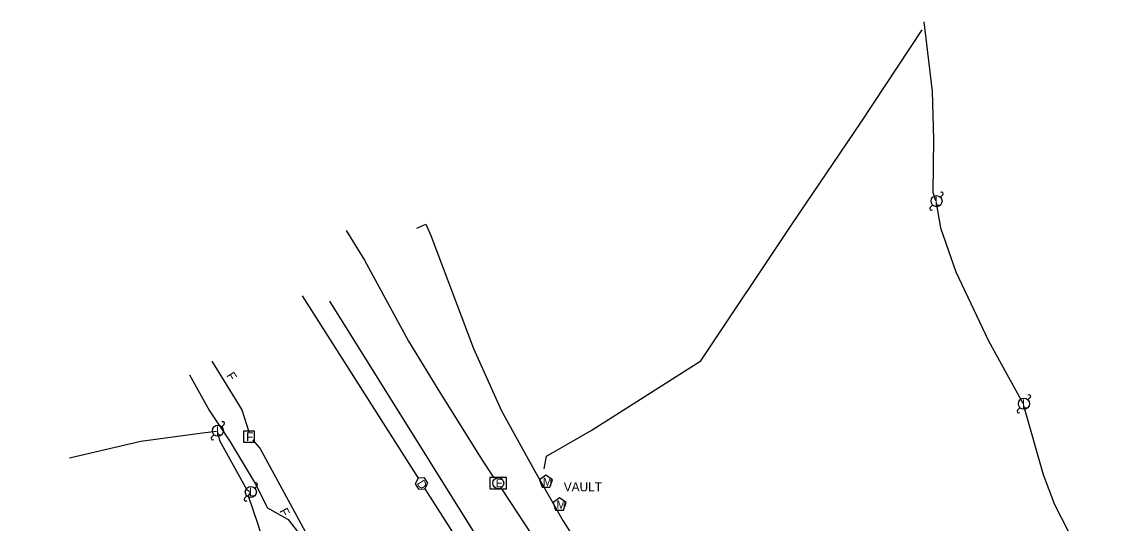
# Model space of a CAD drawing. Extents: x 1741604 to 1825760, y 1164229 to 1194908.
# Drawn here: x 1788051.3 to 1788542.1, y 1183770.9 to 1183996.9 of the extents above; entities that cross this region are included whole.
import ezdxf

# ---------------------------------------------------------------- set-up
doc = ezdxf.new("R2010")
doc.units = 0
for name, color, linetype in [('RD_EX_SU_Elec', 7, 'Continuous'), ('RD_EX_SU_Gas', 7, 'Continuous'), ('RD_EX_SU_H2O', 7, 'Continuous'), ('RD_EX_SU_Pole', 7, 'Continuous'), ('RD_EX_SU_Telecom', 7, 'Continuous'), ('RD_EX_SU_TX_H2O', 7, 'Continuous'), ('RD_EX_SU_TX_Telecom', 7, 'Continuous')]:
    doc.layers.add(name, color=color, linetype=linetype)

# ---------------------------------------------------------------- blocks, each defined once
blk = doc.blocks.new('SUE_WM')
at = {"layer": 'RD_EX_SU_H2O'}
blk.add_lwpolyline([(0, 3.05), (-2.9, 0.94), (-1.79, -2.47), (1.79, -2.47), (2.9, 0.94)], close=True, dxfattribs=at)
blk.add_text('M', height=3.75, dxfattribs=at).set_placement((-1.43, -1.88))

msp = doc.modelspace()

# ---------------------------------------------------------------- linework, layer by layer
at = {"layer": 'RD_EX_SU_Elec'}
for points in [[(1788458.01, 1183996.92), (1788461.77, 1183965.48), (1788462.39, 1183943.97), (1788462.12, 1183920.08), (1788463.28, 1183916.42)], [(1788463.63, 1183915.38), (1788465.57, 1183904.08), (1788472.46, 1183884.24), (1788487.22, 1183853.04), (1788502.67, 1183825.07)], [(1788197.52, 1183902.86), (1788205.84, 1183889.48), (1788225.65, 1183852.96), (1788238.84, 1183831.27), (1788258.92, 1183799.26), (1788263.83, 1183791.85)], [(1788502.94, 1183824.03), (1788511.78, 1183792.86), (1788517.03, 1183779.34), (1788540.86, 1183732.77), (1788542.1, 1183732.22)], [(1788072.85, 1183800.43), (1788105.03, 1183807.94), (1788132.72, 1183811.6), (1788139.05, 1183812.35)], [(1788139.59, 1183811.98), (1788140.51, 1183808.16), (1788147.36, 1183795.66), (1788152.83, 1183785.9), (1788154.16, 1183785.23)], [(1788154.27, 1183784.6), (1788153.45, 1183783.2), (1788157.66, 1183770.44), (1788163.13, 1183753.07), (1788169.12, 1183740.27)], [(1788267.93, 1183785.96), (1788281.5, 1183765.34), (1788301.05, 1183738.22), (1788315.42, 1183716.09), (1788322.04, 1183702.13), (1788344.59, 1183668.1), (1788364.36, 1183642.25), (1788376.14, 1183629.81), (1788408.98, 1183603.56), (1788419.49, 1183593.98), (1788443.59, 1183579.95), (1788457.69, 1183566.89)]]:
    msp.add_lwpolyline(points, dxfattribs=at)
msp.add_lwpolyline([(1788269.86, 1183791.45), (1788262.42, 1183791.45), (1788262.42, 1183786.45), (1788269.86, 1183786.45)], close=True, dxfattribs=at)
msp.add_circle((1788266.14, 1183788.95), 2.47, dxfattribs=at)
at = {"layer": 'RD_EX_SU_Gas'}
for p, q in [((1788177.66, 1183873.42), (1788229.98, 1183791.25)), ((1788233.08, 1183786.38), (1788290.45, 1183696.27))]:
    msp.add_line(p, q, dxfattribs=at)
msp.add_lwpolyline([(1788233.08, 1183786.38), (1788234.41, 1183788.94), (1788232.86, 1183791.38), (1788229.98, 1183791.25), (1788228.65, 1183788.69), (1788230.2, 1183786.25)], close=True, dxfattribs=at)
at = {"layer": 'RD_EX_SU_H2O'}
for points in [[(1788286.9, 1183795.45), (1788287.86, 1183801.08), (1788307.97, 1183812.62), (1788357.48, 1183844.1), (1788398.56, 1183905.52), (1788429.79, 1183951.73), (1788457.27, 1183993.28)], [(1788229.41, 1183903.94), (1788233.43, 1183905.72), (1788235.73, 1183900.64), (1788255.02, 1183849.63), (1788267.63, 1183821.5), (1788282.62, 1183794.43), (1788295.32, 1183772.14)], [(1788190.07, 1183871.02), (1788257.58, 1183762.93), (1788303.91, 1183698.73)], [(1788295.32, 1183772.14), (1788303.92, 1183758.42), (1788316.07, 1183737.45), (1788330.52, 1183715.26), (1788335.33, 1183706.88)]]:
    msp.add_lwpolyline(points, dxfattribs=at)
at = {"layer": 'RD_EX_SU_Pole'}
for p, q in [((1788465.55, 1183917.84), (1788466.61, 1183918.9)), ((1788460.96, 1183913.25), (1788462.02, 1183914.31)), ((1788504.94, 1183826.5), (1788506, 1183827.56)), ((1788500.34, 1183821.91), (1788501.4, 1183822.97)), ((1788141.49, 1183814.33), (1788142.55, 1183815.39)), ((1788136.89, 1183809.74), (1788137.95, 1183810.8)), ((1788156.35, 1183786.76), (1788157.41, 1183787.82)), ((1788151.75, 1183782.16), (1788152.81, 1183783.22))]:
    msp.add_line(p, q, dxfattribs=at)
for centre in [(1788463.78, 1183916.08), (1788503.17, 1183824.74), (1788139.72, 1183812.57), (1788154.58, 1183784.99)]:
    msp.add_circle(centre, 2.5, dxfattribs=at)
for centre, start, end in [((1788466.08, 1183919.43), 315, 135), ((1788461.49, 1183912.72), 135, 315), ((1788505.47, 1183828.09), 315, 135), ((1788500.87, 1183821.38), 135, 315), ((1788142.02, 1183815.93), 315, 135), ((1788137.42, 1183809.21), 135, 315), ((1788156.88, 1183788.35), 315, 135), ((1788152.28, 1183781.63), 135, 315)]:
    msp.add_arc(centre, 0.75, start, end, dxfattribs=at)
at = {"layer": 'RD_EX_SU_Telecom'}
for points in [[(1788137.06, 1183844), (1788150.57, 1183821.96), (1788153.65, 1183812.16)], [(1788126.96, 1183837.83), (1788135.95, 1183821.54), (1788145.27, 1183807.65), (1788156.58, 1183788.77), (1788162.1, 1183777.85), (1788171.45, 1183772.54), (1788177.97, 1183763.96), (1788189.88, 1183733.88), (1788197.36, 1183724.72), (1788200.19, 1183716.92), (1788200.39, 1183704.9), (1788200.18, 1183689.82), (1788195.72, 1183647.8), (1788198.54, 1183642.45), (1788213.56, 1183615.04), (1788222.05, 1183598.67), (1788235.57, 1183579.78), (1788244.04, 1183571.95), (1788266.31, 1183556.88)], [(1788051.29, 1183564.14), (1788084.42, 1183579.44), (1788117.25, 1183594.8), (1788139.21, 1183607.89), (1788149.94, 1183615.25), (1788153.66, 1183618.61), (1788170.9, 1183630.9), (1788187.67, 1183642.57), (1788206.29, 1183654.8), (1788213.76, 1183662.51), (1788216.24, 1183670.16), (1788215.71, 1183679.67), (1788213.84, 1183690.49), (1788206.85, 1183710.92), (1788187.89, 1183750.92), (1788171.57, 1183781.18), (1788158.59, 1183804.81), (1788155.49, 1183808.54)]]:
    msp.add_lwpolyline(points, dxfattribs=at)
msp.add_lwpolyline([(1788156.22, 1183812.38), (1788151.22, 1183812.38), (1788151.22, 1183807.39), (1788156.22, 1183807.39)], close=True, dxfattribs=at)

# ---------------------------------------------------------------- block references
at = {"layer": 'RD_EX_SU_H2O'}
for p in [(1788287.67, 1183789.57), (1788293.8, 1183779.29)]:
    msp.add_blockref('SUE_WM', p, dxfattribs=at)

# ---------------------------------------------------------------- texts
at = {"layer": 'RD_EX_SU_Elec'}
msp.add_text('E', height=3.53, dxfattribs=at).set_placement((1788265.04, 1183787.18))
at = {"layer": 'RD_EX_SU_Gas'}
msp.add_text('D', height=3.75, rotation=302.4835, dxfattribs=at).set_placement((1788229.27, 1183788.87))
at = {"layer": 'RD_EX_SU_Pole'}
for p in [(1788462.92, 1183914.08), (1788502.31, 1183822.74), (1788138.86, 1183810.57), (1788153.72, 1183782.99)]:
    msp.add_text('L', height=4, dxfattribs=at).set_placement(p)
at = {"layer": 'RD_EX_SU_Telecom'}
msp.add_text('F', height=4, dxfattribs=at).set_placement((1788152.48, 1183807.89))
at = {"layer": 'RD_EX_SU_TX_H2O'}
msp.add_text('VAULT', height=4, dxfattribs=at).set_placement((1788295.68, 1183785.29))
at = {"layer": 'RD_EX_SU_TX_Telecom'}
for rotation, p in [(301.5234, (1788143.38, 1183837.51)), (298.3331, (1788167.32, 1183776.43))]:
    msp.add_text('F', height=4, rotation=rotation, dxfattribs=at).set_placement(p)

doc.saveas('drawing.dxf')
